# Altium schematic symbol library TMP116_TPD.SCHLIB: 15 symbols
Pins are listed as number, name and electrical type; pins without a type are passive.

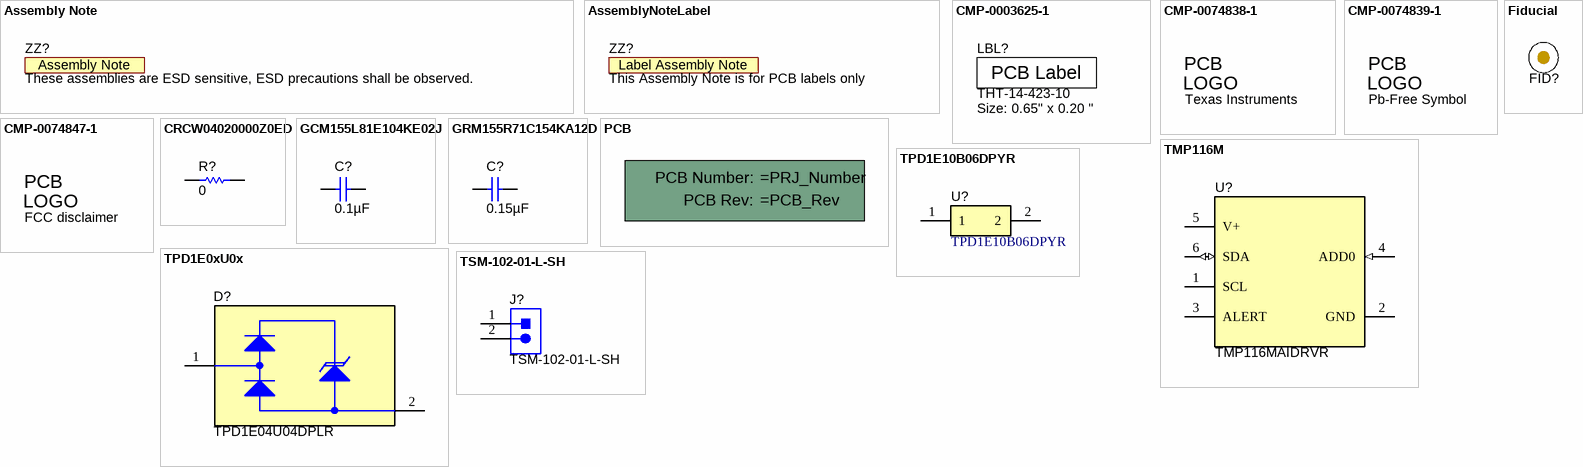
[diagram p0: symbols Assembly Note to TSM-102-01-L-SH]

## Assembly Note
designator ZZ?, comment These assemblies are ESD sensitive, ESD precautions shall be observed.  (no BOM)
CompType: AssemblyNote
footprint AssemblyNote (Assembly Note)

## AssemblyNoteLabel
designator ZZ?, comment This Assembly Note is for PCB labels only  (no BOM)
Key: AssemblyNoteLabel
footprint AssemblyNoteLabel (Assembly Note for PCB Labels)

## CMP-0003625-1
designator LBL?, comment THT-14-423-10  Note: Size: 0.65" x 0.20 "
Thermal Transfer Printable Labels, 0.650" W x 0.200" H - 10,000 per roll; Manufacturer: Brady; CompType: Label
footprint Label_650x200 (Thermal Transfer Label)

## CMP-0074838-1
designator Logo?, comment Texas Instruments  (no BOM)
Texas Instrument Corporate Signature; SymbolCreator: a0412235; Lib Reference: TI_Logo; Library Reference: Logo
footprint TI_Horizontal_Overlay_Medium
footprint TI_Horizontal_Overlay_Small
footprint TI_Stacked_SolderMask_Small
footprint TI_Stacked_SolderMask_Small_Vertical
footprint TI_Symbol_Overlay_Medium
footprint TI_Symbol_Overlay_Small
footprint TI_Symbol_SolderMask_Medium
footprint TI_Symbol_SolderMask_Small
footprint TI_Horizontal_SolderMask_Medium
footprint TI_Horizontal_SolderMask_Small
footprint TI_Stacked_Overlay_Medium
footprint TI_Stacked_Overlay_Medium_Vertical
footprint TI_Stacked_Overlay_Small
footprint TI_Stacked_Overlay_Small_Vertical
footprint TI_Stacked_SolderMask_Medium
footprint TI_Stacked_SolderMask_Medium_Vertical

## CMP-0074839-1
designator Logo?, comment Pb-Free Symbol  (no BOM)
SymbolCreator: a0412235; Library Reference: Logo
footprint Pb-Free_Overlay_Medium
footprint Pb-Free_Overlay_Small

## CMP-0074847-1
designator Logo?, comment FCC disclaimer  (no BOM)
FCC_disclaimer; Library Reference: Logo
footprint FCC_disclaimer
footprint FCC_disclaimer_stacked

## CRCW04020000Z0ED
designator R?  ValueDisplayed: 0  (hidden comment: CRCW04020000Z0ED)
RES, 0, 5%, 0.063 W, 0402; Manufacturer: Vishay-Dale; CompType: Resistor; Value: 0; Value_Code: 0000; Tolerance_%: 5; Power_W: 0.063; Value2: 0.063W; VDC_V: 50; TempCo: 200 ppm/C; EIA_Code: E24; U/M: EA; AEC Category: Q200; SizeArea_mm2: 0.5; SizeX_mm: 1; SizeZ_mm: 0.6; Green_Lifecycle: Active; Green_REACh: Passed
signal-integrity model Resistor
simulation model Resistor
footprint 0402
footprint 0402M
footprint 0402L
footprint 0402S
pins: 1, 2

## Fiducial
designator FID?  (value not drawn)
Fiducial mark.  There is nothing to buy or mount.
footprint Fiducial10-30
footprint Fiducial15-30
footprint Fiducial10-20
footprint Fiducial20-40
footprint Fiducial6.4-20

## GCM155L81E104KE02J
designator C?  ValueDisplayed: 0.1µF  (hidden comment: GCM155L81E104KE02J)
CAP, CERM, 0.1 µF, 50 V,+/- 10%, X8L, 0402; Manufacturer: MuRata; Polarized: N; CompType: Capacitor; Value: 0.1uF; U/M: EA; Cap_F: 0.0000001; Tolerance_%: 10; VDC_V: 50; Value2: 50V; TaMin_C: -55; TaMax_C: 150; Cap_Case: 0402; AEC Category: Q200; AEC Qualified: Y; AEC Grade: 1; SizeArea_mm2: 0.5; SizeAreaWB_mm2: 3; SizeZ_mm: 0.6
signal-integrity model Cap
simulation model Cap
footprint 0402
footprint 0402M
footprint 0402L
footprint 0402S
pins: 1, 2

## GRM155R71C154KA12D
designator C?  ValueDisplayed: 0.15µF  (hidden comment: GRM155R71C154KA12D)
CAP, CERM, 0.15 µF, 16 V,+/- 10%, X7R, 0402; Manufacturer: MuRata; Polarized: N; CompType: Capacitor; Value: 0.15uF; U/M: EA; Cap_F: 0.00000015; Tolerance_%: 10; VDC_V: 16; Value2: 16V; TaMin_C: -55; TaMax_C: 125; Cap_Case: 0402; AEC Category: Q200; SizeArea_mm2: 0.5; SizeAreaWB_mm2: 3; SizeX_mm: 1; SizeZ_mm: 0.6
signal-integrity model Cap
simulation model Cap
footprint 0402
footprint 0402M
footprint 0402L
footprint 0402S
pins: 1, 2

## PCB
designator !PCB?, comment Printed Circuit Board  (value not drawn)  (mechanical)
Manufacturer: Any; CompType: PCB
1 alternate drawing of the same symbol

## TMP116M
designator U?, comment TMP116MAIDRVR
High-Accuracy, Low-Power, Digital Temperature Sensor With SMBus- and I2C-Compatible Interface, DRV0006B (WSON-6); Alternate PartNumber: TMP116MAIDRVT; Alternate Manufacturer: Texas Instruments; SizeAreaWB_mm2: 9.0; SizeZ_mm: 0.8; SizeX_mm: 2.0; SizeArea_mm2: 4.0; CompType: IC; AEC Qualified: N; AEC Category: Q200
footprint DRV0006B (SON, 6-Leads, Body 2x2mm, Pitch 0.65mm, TI Recommended)
pins: 1 SCL (oc), 2 GND (power), 3 ALERT (oc), 4 ADD0 (in), 5 V+ (power), 6 SDA (io)

## TPD1E0xU0x
designator D?, comment TPD1E04U04DPLR
1-Channel ESD Protection Diode With Low Dynamic Resistance for HDMI 2.0 and USB 3.0, DPL0002A (X2SON-2); Alternate PartNumber: TPD1E04U04DPLT; Alternate Manufacturer: Texas Instruments; SizeAreaWB_mm2: 2.08; U/M: EA; SizeZ_mm: 0.32; SizeX_mm: 0.6; SizeY_mm: 0.3; SizeArea_mm2: 0.18; CompType: IC
footprint DPL0002A (R-PX2SON-N2)
footprint DPY0002A (R-PX2SON-N2)
pins: 1 I/O, 2 GND

## TPD1E10B06DPYR
designator U?
ESD in 0402 Package with 10 pF Capacitance and 6 V Breakdown, 1 Channel, -40 to +125 degC, 2-pin X2SON (DPY), Green (RoHS & no Sb/Br); Manufacturer: Texas Instruments; Alternate PartNumber: Equivalent; Breakdown Voltage(Min)(V): 6; Eco-Plan: TBD; IEC 61000-4-2 Air-Gap(+/- kV): 30; IO Capacitance(Typ)(pF): 10; SubFamily: ESD Solution
footprint DPY0002A (R-PX2SON-N2)
pins: 1, 2

## TSM-102-01-L-SH
designator J?
Header, 2.54mm, 2x1, Gold with Tin Tail, R/A, SMT; Manufacturer: Samtec; SymbolCreator: a0412235; Pitch_mm: 2.54; Gender: Male; Shrouded: N; Row_Count: 1; Current_A: 5.4; Voltage_V: 475; Cert_CSA: Y
footprint Samtec_TSM-102-01-x-SH
pins: 1, 2
1 alternate drawing of the same symbol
